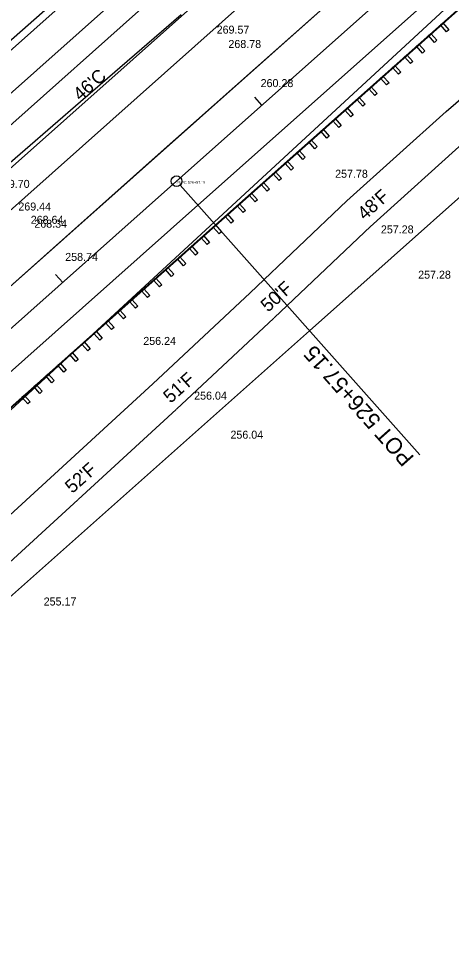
# Model space of a CAD drawing. Extents: x 49683 to 58852, y 49525 to 54803.
# Drawn here: x 54122.5 to 54284.8, y 51789.8 to 52139.1 of the extents above; entities that cross this region are included whole.
import ezdxf

# ---------------------------------------------------------------- set-up
doc = ezdxf.new("R2010")
doc.units = 0
for name, color, linetype in [('Level 1', 7, 'Continuous'), ('Level 11', 7, 'Continuous'), ('Level 13', 7, 'Continuous'), ('Level 18', 7, 'Continuous'), ('Level 19', 7, 'Continuous'), ('Level 20', 7, 'Continuous'), ('Level 27', 7, 'Continuous'), ('Level 3', 7, 'Continuous'), ('Level 32', 7, 'Continuous'), ('Level 33', 7, 'Continuous'), ('Level 48', 7, 'Continuous'), ('Level 51', 7, 'Continuous'), ('Level 8', 7, 'Continuous')]:
    doc.layers.add(name, color=color, linetype=linetype)

msp = doc.modelspace()

# ---------------------------------------------------------------- linework, layer by layer
at = {"layer": 'Level 1'}
msp.add_line((52544.81, 50683.3), (55534.58, 53340.86), dxfattribs=at)
at = {"layer": 'Level 11'}
for p, q in [((53944.24, 51830.77), (54450.3, 52297.6)), ((53894.91, 51911.93), (54324.2, 52292.62))]:
    msp.add_line(p, q, dxfattribs=at)
at = {"layer": 'Level 13'}
for p, q in [((55279.53, 53070), (53969.03, 51905.11)), ((54949.37, 52864.83), (53925.18, 51954.44))]:
    msp.add_line(p, q, dxfattribs=at)
at = {"layer": 'Level 18'}
for p, q in [((54145.7, 52107.97), (54183.54, 52140.66)), ((54282.84, 52104.2), (54320.49, 52137.11)), ((54107.86, 52075.28), (54145.7, 52107.97)), ((54245.68, 52070.75), (54282.84, 52104.2)), ((54254.38, 52061.09), (54291.54, 52094.54)), ((54209.41, 52036.3), (54245.68, 52070.75)), ((54218.36, 52026.87), (54254.64, 52061.32)), ((54172.86, 52002.16), (54209.41, 52036.3)), ((54181.73, 51992.66), (54218.28, 52026.8)), ((54136.01, 51968.35), (54172.86, 52002.16)), ((54144.8, 51958.77), (54181.65, 51992.58)), ((54099.1, 51934.61), (54136.01, 51968.35)), ((54107.87, 51925.02), (54144.78, 51958.75))]:
    msp.add_line(p, q, dxfattribs=at)
at = {"layer": 'Level 19'}
for p, q in [((54181.77, 52078.16), (56150.85, 53828.45)), ((54213.79, 52106.63), (54211.13, 52109.62)), ((52714.15, 50773.62), (54181.77, 52078.16)), ((54273, 51975.52), (54183.1, 52076.67)), ((54139.05, 52040.19), (54136.39, 52043.18))]:
    msp.add_line(p, q, dxfattribs=at)
msp.add_circle((54181.77, 52078.16), 2, dxfattribs=at)
at = {"layer": 'Level 20'}
for p, q in [((54173.8, 52087.13), (55269.45, 53061.04)), ((54189.74, 52069.19), (55278.86, 53037.3)), ((53930.77, 51871.11), (54173.8, 52087.13)), ((53946.72, 51853.17), (54189.74, 52069.19))]:
    msp.add_line(p, q, dxfattribs=at)
at = {"layer": 'Level 27'}
for p, q in [((54196.38, 52061.72), (55282.79, 53027.4)), ((54196.55, 52061.53), (55282.95, 53027.22)), ((54280.73, 52136.69), (54281.61, 52137.47)), ((54282.99, 52134.15), (54280.73, 52136.69)), ((54281.61, 52137.47), (54283.87, 52134.93)), ((54276.24, 52132.7), (54277.13, 52133.49)), ((54277.13, 52133.49), (54279.38, 52130.95)), ((54283.87, 52134.93), (54282.99, 52134.15)), ((54271.76, 52128.72), (54272.64, 52129.5)), ((54272.64, 52129.5), (54274.9, 52126.96)), ((54278.5, 52130.16), (54276.24, 52132.7)), ((54279.38, 52130.95), (54278.5, 52130.16)), ((54274.02, 52126.17), (54271.76, 52128.72)), ((54274.9, 52126.96), (54274.02, 52126.17)), ((54267.27, 52124.73), (54268.16, 52125.51)), ((54269.53, 52122.19), (54267.27, 52124.73)), ((54268.16, 52125.51), (54270.42, 52122.97)), ((54270.42, 52122.97), (54269.53, 52122.19)), ((54262.79, 52120.74), (54263.67, 52121.53)), ((54265.05, 52118.2), (54262.79, 52120.74)), ((54263.67, 52121.53), (54265.93, 52118.99)), ((54265.93, 52118.99), (54265.05, 52118.2)), ((54258.3, 52116.76), (54259.19, 52117.54)), ((54260.56, 52114.22), (54258.3, 52116.76)), ((54259.19, 52117.54), (54261.45, 52115)), ((54253.82, 52112.77), (54254.7, 52113.56)), ((54256.08, 52110.23), (54253.82, 52112.77)), ((54254.7, 52113.56), (54256.96, 52111.01)), ((54261.45, 52115), (54260.56, 52114.22)), ((54249.34, 52108.78), (54250.22, 52109.57)), ((54251.59, 52106.24), (54249.34, 52108.78)), ((54250.22, 52109.57), (54252.48, 52107.03)), ((54256.96, 52111.01), (54256.08, 52110.23)), ((54244.85, 52104.8), (54245.73, 52105.58)), ((54245.73, 52105.58), (54247.99, 52103.04)), ((54252.48, 52107.03), (54251.59, 52106.24)), ((54240.37, 52100.81), (54241.25, 52101.6)), ((54241.25, 52101.6), (54243.51, 52099.06)), ((54247.11, 52102.26), (54244.85, 52104.8)), ((54247.99, 52103.04), (54247.11, 52102.26)), ((54242.62, 52098.27), (54240.37, 52100.81)), ((54243.51, 52099.06), (54242.62, 52098.27)), ((54235.88, 52096.83), (54236.77, 52097.61)), ((54238.14, 52094.28), (54235.88, 52096.83)), ((54236.77, 52097.61), (54239.02, 52095.07)), ((54239.02, 52095.07), (54238.14, 52094.28)), ((54231.4, 52092.84), (54232.28, 52093.63)), ((54233.66, 52090.3), (54231.4, 52092.84)), ((54232.28, 52093.63), (54234.54, 52091.08)), ((54234.54, 52091.08), (54233.66, 52090.3)), ((54226.91, 52088.85), (54227.8, 52089.64)), ((54229.17, 52086.31), (54226.91, 52088.85)), ((54227.8, 52089.64), (54230.06, 52087.1)), ((54222.43, 52084.87), (54223.31, 52085.65)), ((54224.69, 52082.33), (54222.43, 52084.87)), ((54223.31, 52085.65), (54225.57, 52083.11)), ((54230.06, 52087.1), (54229.17, 52086.31)), ((54217.94, 52080.88), (54218.83, 52081.67)), ((54220.2, 52078.34), (54217.94, 52080.88)), ((54218.83, 52081.67), (54221.09, 52079.13)), ((54225.57, 52083.11), (54224.69, 52082.33)), ((54213.46, 52076.9), (54214.34, 52077.68)), ((54215.72, 52074.35), (54213.46, 52076.9)), ((54214.34, 52077.68), (54216.6, 52075.14)), ((54221.09, 52079.13), (54220.2, 52078.34)), ((54208.98, 52072.91), (54209.86, 52073.69)), ((54209.86, 52073.69), (54212.12, 52071.15)), ((54216.6, 52075.14), (54215.72, 52074.35)), ((54211.23, 52070.37), (54208.98, 52072.91)), ((54212.12, 52071.15), (54211.23, 52070.37)), ((54204.49, 52068.92), (54205.37, 52069.71)), ((54206.75, 52066.38), (54204.49, 52068.92)), ((54205.37, 52069.71), (54207.63, 52067.17)), ((54207.63, 52067.17), (54206.75, 52066.38)), ((54200.01, 52064.94), (54200.89, 52065.72)), ((54202.26, 52062.4), (54200.01, 52064.94)), ((54200.89, 52065.72), (54203.15, 52063.18)), ((54203.15, 52063.18), (54202.26, 52062.4)), ((53953.36, 51845.7), (54196.38, 52061.72)), ((53953.53, 51845.51), (54196.55, 52061.53)), ((54195.52, 52060.95), (54196.41, 52061.74)), ((54197.78, 52058.41), (54195.52, 52060.95)), ((54196.41, 52061.74), (54198.66, 52059.19)), ((54191.04, 52056.96), (54191.92, 52057.75)), ((54193.3, 52054.42), (54191.04, 52056.96)), ((54191.92, 52057.75), (54194.18, 52055.21)), ((54198.66, 52059.19), (54197.78, 52058.41)), ((54186.55, 52052.98), (54187.44, 52053.76)), ((54188.81, 52050.44), (54186.55, 52052.98)), ((54187.44, 52053.76), (54189.69, 52051.22)), ((54194.18, 52055.21), (54193.3, 52054.42)), ((54182.07, 52048.99), (54182.95, 52049.78)), ((54184.33, 52046.45), (54182.07, 52048.99)), ((54182.95, 52049.78), (54185.21, 52047.24)), ((54189.69, 52051.22), (54188.81, 52050.44)), ((54177.58, 52045.01), (54178.47, 52045.79)), ((54178.47, 52045.79), (54180.73, 52043.25)), ((54185.21, 52047.24), (54184.33, 52046.45)), ((54179.84, 52042.46), (54177.58, 52045.01)), ((54180.73, 52043.25), (54179.84, 52042.46)), ((54173.1, 52041.02), (54173.98, 52041.8)), ((54175.36, 52038.48), (54173.1, 52041.02)), ((54173.98, 52041.8), (54176.24, 52039.26)), ((54176.24, 52039.26), (54175.36, 52038.48)), ((54168.62, 52037.03), (54169.5, 52037.82)), ((54170.87, 52034.49), (54168.62, 52037.03)), ((54169.5, 52037.82), (54171.76, 52035.28)), ((54171.76, 52035.28), (54170.87, 52034.49)), ((54164.13, 52033.05), (54165.01, 52033.83)), ((54166.39, 52030.51), (54164.13, 52033.05)), ((54165.01, 52033.83), (54167.27, 52031.29)), ((54159.65, 52029.06), (54160.53, 52029.85)), ((54161.9, 52026.52), (54159.65, 52029.06)), ((54160.53, 52029.85), (54162.79, 52027.3)), ((54167.27, 52031.29), (54166.39, 52030.51)), ((54155.16, 52025.08), (54156.05, 52025.86)), ((54157.42, 52022.53), (54155.16, 52025.08)), ((54156.05, 52025.86), (54158.3, 52023.32)), ((54162.79, 52027.3), (54161.9, 52026.52)), ((54150.68, 52021.09), (54151.56, 52021.87)), ((54152.94, 52018.55), (54150.68, 52021.09)), ((54151.56, 52021.87), (54153.82, 52019.33)), ((54158.3, 52023.32), (54157.42, 52022.53)), ((54146.19, 52017.1), (54147.08, 52017.89)), ((54147.08, 52017.89), (54149.33, 52015.35)), ((54153.82, 52019.33), (54152.94, 52018.55)), ((54148.45, 52014.56), (54146.19, 52017.1)), ((54149.33, 52015.35), (54148.45, 52014.56)), ((54141.71, 52013.12), (54142.59, 52013.9)), ((54143.97, 52010.58), (54141.71, 52013.12)), ((54142.59, 52013.9), (54144.85, 52011.36)), ((54144.85, 52011.36), (54143.97, 52010.58)), ((54137.22, 52009.13), (54138.11, 52009.92)), ((54139.48, 52006.59), (54137.22, 52009.13)), ((54138.11, 52009.92), (54140.37, 52007.37)), ((54140.37, 52007.37), (54139.48, 52006.59)), ((54132.74, 52005.14), (54133.62, 52005.93)), ((54135, 52002.6), (54132.74, 52005.14)), ((54133.62, 52005.93), (54135.88, 52003.39)), ((54128.25, 52001.16), (54129.14, 52001.94)), ((54130.51, 51998.62), (54128.25, 52001.16)), ((54129.14, 52001.94), (54131.4, 51999.4)), ((54135.88, 52003.39), (54135, 52002.6)), ((54123.77, 51997.17), (54124.65, 51997.96)), ((54126.03, 51994.63), (54123.77, 51997.17)), ((54124.65, 51997.96), (54126.91, 51995.42)), ((54131.4, 51999.4), (54130.51, 51998.62)), ((54126.91, 51995.42), (54126.03, 51994.63))]:
    msp.add_line(p, q, dxfattribs=at)
at = {"layer": 'Level 3'}
for p, q in [((54069.54, 52054.72), (54330.23, 52286.79)), ((54083.39, 52035.12), (54346.38, 52269.23))]:
    msp.add_line(p, q, dxfattribs=at)
at = {"layer": 'Level 33'}
for p, q in [((54231.59, 52022.1), (55608.96, 53246.42)), ((53814.15, 51651.04), (54231.6, 52022.1))]:
    msp.add_line(p, q, dxfattribs=at)
at = {"layer": 'Level 8'}
msp.add_line((54015.78, 52039), (54838.64, 52769.14), dxfattribs=at)

# ---------------------------------------------------------------- texts
at = {"layer": 'Level 19'}
msp.add_text('POT 526+57.15', height=6, rotation=131.6334, dxfattribs=at).set_placement((54271.21, 51974.64))
at = {"layer": 'Level 32'}
for s, p in [('269.57', (54196.8, 52133.44)), ('268.78', (54201.21, 52128.07)), ('260.28', (54213.29, 52113.4)), ('257.78', (54241.24, 52079.42)), ('269.70', (54114.38, 52075.63)), ('269.44', (54122.42, 52067.15)), ('268.64', (54127.06, 52062.16)), ('268.34', (54128.42, 52060.7)), ('257.28', (54258.4, 52058.57)), ('258.74', (54140, 52048.25)), ('257.28', (54272.38, 52041.59)), ('256.24', (54169.28, 52016.77)), ('256.04', (54188.36, 51996.26)), ('256.04', (54201.98, 51981.62)), ('255.17', (54131.92, 51919.1))]:
    msp.add_text(s, height=3, dxfattribs=at).set_placement(p)
at = {"layer": 'Level 48'}
for s, p in [("46'C", (54145.7, 52107.97)), ("48'F", (54252.33, 52063.27)), ("50'F", (54216.05, 52028.82)), ("51'F", (54179.5, 51994.68)), ("52'F", (54142.65, 51960.88))]:
    msp.add_text(s, height=5, rotation=41.6334, dxfattribs=at).set_placement(p)
at = {"layer": 'Level 51'}
msp.add_text('26 PC 526+57.15', height=1, dxfattribs=at).set_placement((54181.77, 52077.16))

doc.saveas('drawing.dxf')
